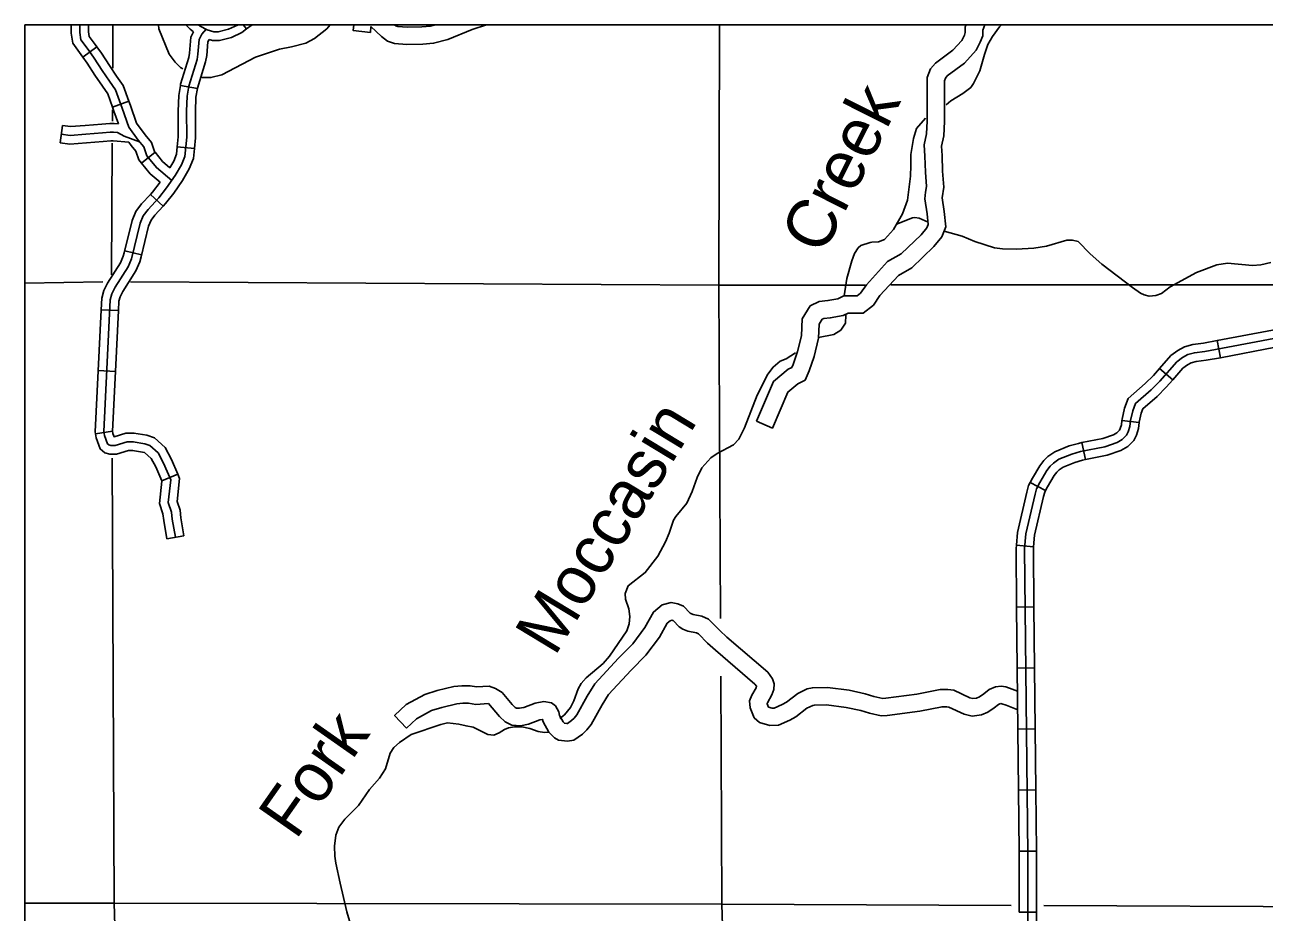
# Model space of a CAD drawing. Extents: x 1377389 to 1380723, y 1168351 to 1170484.
# Drawn here: x 1378340.6 to 1378554.8, y 1169425.9 to 1169579.4 of the extents above; entities that cross this region are included whole.
import ezdxf

# ---------------------------------------------------------------- set-up
doc = ezdxf.new("R2010")
doc.units = 0
doc.layers.add('B_Fill', color=7, linetype='Continuous')
doc.layers.add('B_Text', color=7, linetype='Continuous')

msp = doc.modelspace()

# ---------------------------------------------------------------- linework, layer by layer
at = {"layer": 'B_Fill'}
for p, q in [((1378378.92, 1169578.7), (1378378.37, 1169579.43)), ((1378350.63, 1169573.84), (1378353.04, 1169575.63)), ((1378367.5, 1169568.93), (1378370.45, 1169568.43)), ((1378355.77, 1169565.2), (1378358.6, 1169566.21)), ((1378346.73, 1169559.01), (1378347.11, 1169561.98)), ((1378360.79, 1169555.49), (1378363.12, 1169557.38)), ((1378369.95, 1169558), (1378366.97, 1169558.31)), ((1378362.33, 1169550.09), (1378364.52, 1169548.04)), ((1378360.79, 1169539.64), (1378357.88, 1169540.35)), ((1378353.8, 1169530.14), (1378356.8, 1169530)), ((1378546.71, 1169524.8), (1378547.27, 1169521.85)), ((1378356.29, 1169519.46), (1378353.3, 1169519.61)), ((1378536.76, 1169519.97), (1378539.02, 1169517.99)), ((1378530.26, 1169511.01), (1378533.24, 1169510.65)), ((1378352.82, 1169508.66), (1378355.78, 1169509.12)), ((1378523.34, 1169507.15), (1378523.93, 1169504.21)), ((1378367.04, 1169501.73), (1378364.28, 1169500.55)), ((1378514.41, 1169500.27), (1378517.05, 1169498.85)), ((1378368.12, 1169491.04), (1378365.17, 1169490.53)), ((1378512, 1169489.43), (1378514.99, 1169489.16)), ((1378512.05, 1169478.72), (1378515.05, 1169478.75)), ((1378512.16, 1169468.16), (1378515.16, 1169468.19)), ((1378512.27, 1169457.6), (1378515.27, 1169457.63)), ((1378512.37, 1169447.04), (1378515.37, 1169447.08)), ((1378512.48, 1169436.49), (1378515.48, 1169436.52)), ((1378512.51, 1169425.94), (1378515.51, 1169425.94))]:
    msp.add_line(p, q, dxfattribs=at)
for points in [[(1378348.6, 1169579.43), (1378348.63, 1169577.96), (1378348.89, 1169576.22), (1378350.33, 1169574.25), (1378350.63, 1169573.84)], [(1378350.1, 1169579.43), (1378350.13, 1169578.09), (1378350.32, 1169576.81), (1378351.54, 1169575.14), (1378352.63, 1169573.66), (1378353.98, 1169571.54), (1378355.26, 1169569.68), (1378356.29, 1169568.2), (1378357.44, 1169564.99), (1378358.6, 1169561.72), (1378360.2, 1169559.47), (1378361.17, 1169558.31), (1378361.68, 1169556.77), (1378363.35, 1169554.72), (1378366.01, 1169552.49)], [(1378351.6, 1169579.43), (1378351.63, 1169578.22), (1378351.75, 1169577.39), (1378352.75, 1169576.02), (1378353.04, 1169575.63)], [(1378355.85, 1169579.43), (1378355.81, 1169571.91)], [(1378363.74, 1169579.43), (1378363.8, 1169578.75), (1378365.58, 1169574.36), (1378366.63, 1169572.96), (1378367.54, 1169572.01), (1378367.93, 1169571.78)], [(1378368.43, 1169579.43), (1378369.18, 1169578.69), (1378369.8, 1169578.22)], [(1378370.64, 1169579.43), (1378370.95, 1169579.2), (1378372.13, 1169578.53), (1378373.27, 1169578.19), (1378374.05, 1169578.2), (1378375.84, 1169578.64), (1378377.35, 1169579.36), (1378377.44, 1169579.43)], [(1378370.99, 1169570.39), (1378371.29, 1169570.31), (1378372.79, 1169570.29), (1378374.68, 1169570.77), (1378380.51, 1169573.83), (1378384.62, 1169575.2), (1378386.71, 1169575.59), (1378389.18, 1169576.26), (1378390.68, 1169577.08), (1378392.8, 1169578.7), (1378393.42, 1169579.43)], [(1378372.48, 1169576.89), (1378373.06, 1169576.71), (1378374.24, 1169576.73), (1378376.34, 1169577.24), (1378378.11, 1169578.09), (1378378.92, 1169578.7)], [(1378378.92, 1169578.7), (1378379.89, 1169579.43)], [(1378397.47, 1169579.43), (1378397.36, 1169578.45), (1378400.34, 1169578.11)], [(1378400.45, 1169579.13), (1378400.34, 1169578.11)], [(1378400.45, 1169579.13), (1378402.26, 1169577.37), (1378403.33, 1169576.58), (1378404.49, 1169576.17), (1378406.63, 1169576.02), (1378409.39, 1169576.05), (1378411.26, 1169576.23), (1378413.73, 1169576.87), (1378417.94, 1169578.62), (1378420.44, 1169579.43)], [(1378404.52, 1169579.43), (1378404.75, 1169579.26), (1378405.11, 1169579.13), (1378406.72, 1169579.02), (1378409.23, 1169579.05), (1378410.74, 1169579.19), (1378411.64, 1169579.43)], [(1378460.58, 1169534.4), (1378460.7, 1169579.43)], [(1378503.32, 1169579.43), (1378503.18, 1169579.09), (1378503.18, 1169578.08), (1378503.01, 1169577.63), (1378502.55, 1169576.72), (1378501.04, 1169575.03), (1378498, 1169572.78), (1378497.15, 1169571.78), (1378496.56, 1169570.31), (1378496.56, 1169567.88), (1378496.56, 1169562.74), (1378496.47, 1169560.56), (1378496.06, 1169558.64), (1378496.17, 1169556.7), (1378496.27, 1169553.96), (1378496.45, 1169551.48), (1378496.28, 1169550.45), (1378496.16, 1169549.33)], [(1378506.58, 1169579.43), (1378506.18, 1169578.48), (1378506.18, 1169577.54), (1378505.76, 1169576.43), (1378505.05, 1169575.01), (1378503.06, 1169572.8), (1378500.06, 1169570.57), (1378499.75, 1169570.21), (1378499.56, 1169569.73), (1378499.56, 1169567.88), (1378499.56, 1169562.68), (1378499.45, 1169560.19), (1378499.08, 1169558.41), (1378499.17, 1169556.84), (1378499.26, 1169554.12), (1378499.47, 1169551.34), (1378499.16, 1169549.51)], [(1378499.89, 1169565.56), (1378500.7, 1169566.25), (1378502.74, 1169567.52), (1378504.11, 1169568.58), (1378504.58, 1169569.28), (1378505.71, 1169571.44), (1378506.49, 1169574.31), (1378507.07, 1169576), (1378507.85, 1169577.39), (1378509.09, 1169579.07), (1378509.44, 1169579.43)], [(1378371.95, 1169578.64), (1378371.22, 1169577.78), (1378370.77, 1169576.87), (1378370.54, 1169574.33), (1378370.38, 1169573.41), (1378368.97, 1169568.82), (1378368.67, 1169567.06), (1378368.58, 1169564.46), (1378368.62, 1169559.97), (1378368.28, 1169556.66), (1378367.67, 1169555.2), (1378366.6, 1169553.34), (1378365.13, 1169551.22), (1378363.79, 1169549.5), (1378361.92, 1169547.5), (1378361.09, 1169546.41), (1378360.55, 1169545.1), (1378359.05, 1169538.93), (1378358.46, 1169537.57), (1378356.21, 1169534.04), (1378355.65, 1169532.91), (1378355.36, 1169531.88), (1378354.27, 1169509.09), (1378354.38, 1169508.39), (1378354.89, 1169506.97), (1378355.15, 1169506.76), (1378355.51, 1169506.66), (1378356.25, 1169506.67), (1378358.32, 1169507.3), (1378359.36, 1169507.31), (1378361.35, 1169506.97), (1378362.24, 1169506.66)], [(1378369.8, 1169578.22), (1378369.33, 1169577.28), (1378369.08, 1169574.53), (1378368.94, 1169573.75), (1378367.54, 1169569.16), (1378367.5, 1169568.93)], [(1378372.48, 1169576.89), (1378372.27, 1169576.45), (1378372.06, 1169574.12), (1378371.86, 1169573.04), (1378370.46, 1169568.47), (1378370.45, 1169568.43)], [(1378353.04, 1169575.63), (1378353.87, 1169574.51), (1378355.23, 1169572.37), (1378356.49, 1169570.53), (1378357.63, 1169568.9), (1378358.6, 1169566.21)], [(1378350.63, 1169573.84), (1378351.39, 1169572.81), (1378352.73, 1169570.71), (1378354.03, 1169568.82), (1378354.94, 1169567.51), (1378355.77, 1169565.2)], [(1378367.5, 1169568.93), (1378367.21, 1169567.21), (1378367.11, 1169564.48), (1378367.14, 1169560.04), (1378366.97, 1169558.31)], [(1378370.45, 1169568.43), (1378370.2, 1169566.9), (1378370.11, 1169564.43), (1378370.14, 1169559.9), (1378369.95, 1169558)], [(1378358.6, 1169566.21), (1378358.86, 1169565.49), (1378359.94, 1169562.42), (1378361.39, 1169560.39), (1378362.5, 1169559.06), (1378363.02, 1169557.51), (1378363.12, 1169557.38)], [(1378355.76, 1169564.7), (1378355.75, 1169562.73)], [(1378355.77, 1169565.2), (1378356.03, 1169564.49), (1378356.8, 1169562.31)], [(1378347.11, 1169561.98), (1378348.5, 1169561.81), (1378351.03, 1169561.99), (1378353.9, 1169562.25), (1378355.32, 1169562.38), (1378356.04, 1169562.38), (1378356.8, 1169562.31)], [(1378493.78, 1169556.97), (1378494.22, 1169559.73), (1378494.76, 1169561.47), (1378496.27, 1169563.3)], [(1378346.92, 1169560.5), (1378348.46, 1169560.3), (1378351.15, 1169560.5), (1378354.04, 1169560.75), (1378355.39, 1169560.88), (1378355.97, 1169560.88), (1378356.61, 1169560.82), (1378357.76, 1169560.18), (1378360.42, 1169559.2)], [(1378346.73, 1169559.01), (1378348.42, 1169558.8), (1378351.27, 1169559), (1378354.18, 1169559.26), (1378355.46, 1169559.38), (1378355.89, 1169559.38), (1378358.62, 1169559.11)], [(1378355.73, 1169558.95), (1378355.59, 1169536.2)], [(1378358.62, 1169559.11), (1378359.01, 1169558.55), (1378359.83, 1169557.57), (1378360.34, 1169556.04), (1378360.79, 1169555.49)], [(1378363.12, 1169557.38), (1378364.42, 1169555.77), (1378365.69, 1169554.71)], [(1378369.95, 1169558), (1378369.77, 1169556.29), (1378369.05, 1169554.52), (1378367.89, 1169552.52), (1378366.36, 1169550.32), (1378364.95, 1169548.51), (1378364.52, 1169548.04)], [(1378366.97, 1169558.31), (1378366.83, 1169557.03), (1378366.35, 1169555.85), (1378365.69, 1169554.71)], [(1378360.79, 1169555.49), (1378362.27, 1169553.66), (1378364.02, 1169552.19)], [(1378487.01, 1169541.81), (1378488.18, 1169541.9), (1378489.21, 1169542.27), (1378490.75, 1169543.99), (1378492.33, 1169546.73), (1378493.2, 1169549.11), (1378493.69, 1169553.24), (1378493.79, 1169555.1), (1378493.78, 1169556.97)], [(1378364.02, 1169552.19), (1378362.67, 1169550.46), (1378362.33, 1169550.09)], [(1378362.33, 1169550.09), (1378360.79, 1169548.45), (1378359.81, 1169547.15), (1378359.15, 1169545.56), (1378357.79, 1169540.01)], [(1378499.16, 1169549.51), (1378499.55, 1169547.11), (1378499.83, 1169544.47), (1378499.13, 1169542.73), (1378497.75, 1169541.08), (1378493.91, 1169537.36), (1378491.61, 1169536.09), (1378488.43, 1169532.59), (1378487.31, 1169530.96), (1378485.55, 1169529.55), (1378484.09, 1169529.55), (1378482.91, 1169529.55), (1378482.09, 1169529.14), (1378479.82, 1169528.74), (1378478.75, 1169528.64), (1378478.44, 1169528.49), (1378477.93, 1169527.66), (1378477.83, 1169525.2), (1378477.07, 1169522.05), (1378476.2, 1169519.57), (1378475.49, 1169517.96), (1378474.22, 1169517.33), (1378472.52, 1169515.91), (1378469.84, 1169509.66), (1378467.09, 1169510.84)], [(1378496.16, 1169549.33), (1378496.57, 1169546.72), (1378496.77, 1169544.9), (1378496.52, 1169544.29), (1378495.55, 1169543.12), (1378492.11, 1169539.79), (1378489.72, 1169538.47), (1378486.08, 1169534.45), (1378485.09, 1169533.03), (1378484.5, 1169532.55), (1378484.09, 1169532.55), (1378482.2, 1169532.55), (1378481.14, 1169532.02), (1378479.42, 1169531.72), (1378477.91, 1169531.58), (1378476.34, 1169530.79), (1378474.97, 1169528.57), (1378474.84, 1169525.62), (1378474.19, 1169522.9), (1378473.41, 1169520.68), (1378473.18, 1169520.17), (1378472.57, 1169519.86), (1378470.05, 1169517.75), (1378467.09, 1169510.84)], [(1378364.52, 1169548.04), (1378363.09, 1169546.51), (1378362.43, 1169545.64), (1378362.01, 1169544.62), (1378360.71, 1169539.29)], [(1378491.29, 1169544.92), (1378494.03, 1169546.06), (1378494.43, 1169546.12), (1378495.19, 1169545.95), (1378496.73, 1169545.26)], [(1378499.52, 1169543.71), (1378502.62, 1169542.86), (1378504.84, 1169541.93), (1378508.25, 1169540.85), (1378509.61, 1169540.65), (1378512, 1169540.6), (1378515.05, 1169540.79), (1378517.22, 1169541.16), (1378520.74, 1169542.17), (1378521.68, 1169542.2), (1378522.68, 1169541.97), (1378524.78, 1169539.79), (1378526.75, 1169538.02), (1378532.05, 1169533.96), (1378533.44, 1169532.99), (1378534.08, 1169532.7), (1378534.98, 1169532.51), (1378536.11, 1169532.59), (1378537.07, 1169532.96), (1378538.57, 1169534.12), (1378543.13, 1169536.6), (1378546.65, 1169537.9), (1378548.5, 1169538.18), (1378552.81, 1169537.8), (1378554.23, 1169537.89), (1378555.96, 1169538.33)], [(1378482.21, 1169532.55), (1378482.69, 1169535.52), (1378483.55, 1169538.61), (1378484.04, 1169539.86), (1378484.66, 1169540.83), (1378485.14, 1169541.27), (1378486.71, 1169541.79), (1378487.01, 1169541.81)], [(1378357.79, 1169540.01), (1378357.64, 1169539.4), (1378357.16, 1169538.26), (1378354.93, 1169534.76), (1378354.27, 1169533.44), (1378353.9, 1169532.12), (1378353.8, 1169530.14)], [(1378360.71, 1169539.29), (1378360.5, 1169538.45), (1378359.82, 1169536.85), (1378357.54, 1169533.28), (1378357.08, 1169532.35), (1378356.88, 1169531.64), (1378356.8, 1169530)], [(1378340.61, 1169534.73), (1378354.08, 1169534.96)], [(1378358.88, 1169534.97), (1378460.58, 1169534.4), (1378485.89, 1169534.41)], [(1378460.86, 1169476.75), (1378460.58, 1169534.4)], [(1378490.29, 1169534.42), (1378566.7, 1169534.46)], [(1378353.8, 1169530.14), (1378353.3, 1169519.59)], [(1378356.8, 1169530), (1378356.29, 1169519.45)], [(1378477.83, 1169525.34), (1378480.46, 1169525.87), (1378481.67, 1169526.62), (1378482.44, 1169527.79), (1378482.55, 1169529.21)], [(1378556.53, 1169525.15), (1378544.57, 1169522.9), (1378542.77, 1169522.7), (1378541.62, 1169522.38), (1378540.73, 1169521.87), (1378539.74, 1169521.14), (1378536.81, 1169517.78), (1378535.29, 1169516.28), (1378532.58, 1169513.93), (1378532.12, 1169512.68), (1378531.74, 1169510.97), (1378531.61, 1169509.93), (1378531.32, 1169509.05), (1378531.03, 1169508.44), (1378530.3, 1169507.69), (1378529.43, 1169507.18), (1378527.3, 1169506.45), (1378523.1, 1169505.6), (1378521.59, 1169505.18), (1378519.35, 1169504.27), (1378518.4, 1169503.62), (1378517.85, 1169503.07), (1378517.28, 1169502.31), (1378516.08, 1169500.27), (1378515.5, 1169499.18), (1378515.23, 1169498.24), (1378513.65, 1169491.39), (1378513.42, 1169488.81), (1378513.96, 1169436.06), (1378514.04, 1169404.99)], [(1378557.14, 1169526.73), (1378556.28, 1169526.6), (1378546.71, 1169524.8)], [(1378546.71, 1169524.8), (1378544.35, 1169524.36), (1378542.5, 1169524.15), (1378541.05, 1169523.75), (1378539.92, 1169523.11), (1378538.73, 1169522.23), (1378536.76, 1169519.97)], [(1378557.6, 1169523.77), (1378556.79, 1169523.64), (1378547.27, 1169521.85)], [(1378450.02, 1169487.51), (1378451.37, 1169490.02), (1378452.01, 1169491.51), (1378452.74, 1169493.75), (1378453.13, 1169494.39), (1378455.06, 1169496.7), (1378455.95, 1169498.71), (1378456.82, 1169501.14), (1378457.66, 1169502.79), (1378459.2, 1169504.51), (1378460.28, 1169505.25), (1378463.12, 1169506.8), (1378464.01, 1169507.78), (1378465.02, 1169509.69), (1378467.21, 1169515.38), (1378469.04, 1169519.01), (1378469.95, 1169520.22), (1378471.17, 1169521.26), (1378472.2, 1169521.67), (1378473.83, 1169522.66)], [(1378547.27, 1169521.85), (1378544.79, 1169521.39), (1378543.06, 1169521.19), (1378542.21, 1169520.96), (1378541.57, 1169520.59), (1378540.78, 1169520.01), (1378539.02, 1169517.99)], [(1378353.3, 1169519.59), (1378352.79, 1169509.01), (1378352.82, 1169508.66)], [(1378356.29, 1169519.45), (1378355.78, 1169509.12)], [(1378536.76, 1169519.97), (1378535.73, 1169518.79), (1378534.29, 1169517.36), (1378531.33, 1169514.79), (1378530.7, 1169513.1), (1378530.29, 1169511.22), (1378530.26, 1169511.01)], [(1378539.02, 1169517.99), (1378537.92, 1169516.73), (1378536.33, 1169515.16), (1378533.88, 1169513.03), (1378533.59, 1169512.24), (1378533.25, 1169510.71), (1378533.24, 1169510.65)], [(1378530.26, 1169511.01), (1378530.17, 1169510.25), (1378529.95, 1169509.6), (1378529.81, 1169509.3), (1378529.38, 1169508.86), (1378528.81, 1169508.53), (1378526.92, 1169507.88), (1378523.34, 1169507.15)], [(1378533.24, 1169510.65), (1378533.11, 1169509.6), (1378532.74, 1169508.47), (1378532.3, 1169507.55), (1378531.25, 1169506.48), (1378530.07, 1169505.78), (1378527.7, 1169504.98), (1378523.93, 1169504.21)], [(1378352.82, 1169508.66), (1378352.92, 1169508.01), (1378353.62, 1169506.08), (1378354.45, 1169505.39), (1378355.33, 1169505.16), (1378356.48, 1169505.17), (1378358.55, 1169505.8), (1378359.24, 1169505.81), (1378361.33, 1169505.46)], [(1378355.78, 1169509.12), (1378355.84, 1169508.76), (1378356.05, 1169508.18), (1378358.09, 1169508.79), (1378359.47, 1169508.81), (1378361.73, 1169508.43), (1378363.02, 1169507.98)], [(1378366.65, 1169490.78), (1378366.1, 1169493.92), (1378365.96, 1169495.15), (1378365.42, 1169496.79), (1378365.83, 1169500.74), (1378364.6, 1169503.61), (1378363.65, 1169505.38), (1378362.24, 1169506.66)], [(1378367.04, 1169501.73), (1378365.95, 1169504.26), (1378364.85, 1169506.32), (1378363.02, 1169507.98)], [(1378523.34, 1169507.15), (1378522.76, 1169507.03), (1378521.12, 1169506.58), (1378518.65, 1169505.58), (1378517.45, 1169504.76), (1378516.73, 1169504.04), (1378516.05, 1169503.12), (1378514.8, 1169500.99), (1378514.41, 1169500.27)], [(1378355.72, 1169504.46), (1378356.08, 1169427.5)], [(1378364.28, 1169500.55), (1378363.25, 1169502.95), (1378362.45, 1169504.44), (1378361.33, 1169505.46)], [(1378523.93, 1169504.21), (1378523.46, 1169504.11), (1378522.08, 1169503.73), (1378520.07, 1169502.92), (1378519.38, 1169502.44), (1378519, 1169502.07), (1378518.55, 1169501.46), (1378517.41, 1169499.52), (1378517.05, 1169498.85)], [(1378368.12, 1169491.04), (1378367.59, 1169494.13), (1378367.44, 1169495.47), (1378366.94, 1169496.95), (1378367.36, 1169500.97), (1378367.04, 1169501.73)], [(1378365.17, 1169490.53), (1378364.62, 1169493.71), (1378364.49, 1169494.82), (1378363.89, 1169496.62), (1378364.3, 1169500.51), (1378364.28, 1169500.55)], [(1378514.41, 1169500.27), (1378514.12, 1169499.74), (1378513.8, 1169498.6), (1378512.19, 1169491.62), (1378512, 1169489.43)], [(1378517.05, 1169498.85), (1378516.92, 1169498.6), (1378516.71, 1169497.86), (1378515.16, 1169491.15), (1378514.99, 1169489.16)], [(1378512, 1169489.43), (1378511.95, 1169488.86), (1378512.05, 1169478.72)], [(1378514.99, 1169489.16), (1378514.95, 1169488.75), (1378515.05, 1169478.75)], [(1378433.09, 1169459.44), (1378433.87, 1169460.09), (1378434.91, 1169461.35), (1378435.52, 1169462.48), (1378436.25, 1169464.55), (1378436.78, 1169465.51), (1378437.64, 1169466.47), (1378440.57, 1169468.94), (1378441.69, 1169470.22), (1378444.65, 1169474.62), (1378445.1, 1169475.79), (1378445.2, 1169477.07), (1378445.01, 1169478.39), (1378444.43, 1169480.08), (1378444.4, 1169481.04), (1378444.9, 1169482.41), (1378447.87, 1169484.69), (1378450.02, 1169487.51)], [(1378512.2, 1169464.17), (1378511.3, 1169464.53), (1378510.21, 1169464.92), (1378509.35, 1169465.05), (1378508.38, 1169464.93), (1378507.3, 1169464.47), (1378506.39, 1169463.69), (1378505.62, 1169463.2), (1378505.13, 1169462.98), (1378504.5, 1169462.9), (1378503.97, 1169463.02), (1378501.17, 1169464.34), (1378500.15, 1169464.48), (1378498.85, 1169464.46), (1378494.82, 1169463.68), (1378489.43, 1169462.94), (1378488.9, 1169462.92), (1378487.37, 1169463.25), (1378485.87, 1169463.73), (1378483.08, 1169464.33), (1378479.37, 1169464.81), (1378476.74, 1169464.75), (1378475.83, 1169464.56), (1378474.21, 1169463.79), (1378472.27, 1169462.25), (1378471.53, 1169461.87), (1378470.15, 1169461.25), (1378469.78, 1169461.23), (1378469.16, 1169461.42), (1378468.94, 1169461.96), (1378468.93, 1169462.05), (1378468.98, 1169462.16), (1378469.76, 1169463.51), (1378470.08, 1169464.45), (1378470.15, 1169465.41), (1378469.86, 1169466.33), (1378469.02, 1169467.44), (1378461.96, 1169473.53), (1378460.72, 1169474.65), (1378458.81, 1169476.61), (1378457.64, 1169477.12), (1378456.11, 1169477.44), (1378455.75, 1169477.6), (1378455.62, 1169477.67), (1378454.46, 1169478.87), (1378453.5, 1169479.3), (1378452.34, 1169479.5), (1378450.79, 1169479.11), (1378449.29, 1169477.86), (1378447.79, 1169475.16), (1378445.7, 1169472.34), (1378443.25, 1169469.9), (1378439.13, 1169465.44), (1378437.8, 1169463.31), (1378436.03, 1169460.1), (1378435.56, 1169459.51), (1378435.11, 1169459.08), (1378434.39, 1169458.59), (1378434.33, 1169458.58), (1378433.87, 1169458.62), (1378433.65, 1169458.86), (1378433.05, 1169459.95), (1378432.91, 1169460.57), (1378432.37, 1169461.61), (1378431.63, 1169462.15), (1378430.33, 1169462.36), (1378428.85, 1169462.1), (1378426.85, 1169461.37), (1378426.09, 1169461.22), (1378425.6, 1169461.25), (1378425.37, 1169461.37), (1378424.85, 1169461.85), (1378423.12, 1169463.92)], [(1378512.05, 1169478.72), (1378512.16, 1169468.16)], [(1378515.05, 1169478.75), (1378515.16, 1169468.19)], [(1378512.23, 1169460.93), (1378510.24, 1169461.73), (1378509.49, 1169462), (1378509.31, 1169462.02), (1378509.16, 1169462), (1378508.9, 1169461.89), (1378508.18, 1169461.28), (1378507.05, 1169460.55), (1378505.95, 1169460.07), (1378504.35, 1169459.85), (1378502.97, 1169460.18), (1378500.31, 1169461.43), (1378499.97, 1169461.48), (1378499.16, 1169461.47), (1378495.31, 1169460.72), (1378489.69, 1169459.95), (1378488.64, 1169459.91), (1378486.6, 1169460.35), (1378485.1, 1169460.83), (1378482.57, 1169461.37), (1378479.21, 1169461.8), (1378477.09, 1169461.76), (1378476.8, 1169461.7), (1378475.8, 1169461.23), (1378473.91, 1169459.72), (1378472.83, 1169459.16), (1378470.87, 1169458.29), (1378469.41, 1169458.21), (1378467.58, 1169458.77), (1378466.67, 1169459.57), (1378465.98, 1169461.27), (1378465.89, 1169462.51), (1378466.27, 1169463.47), (1378467.01, 1169464.76), (1378467.1, 1169465.01), (1378466.82, 1169465.37), (1378459.97, 1169471.28), (1378458.64, 1169472.49), (1378457.07, 1169474.09), (1378456.72, 1169474.25), (1378455.21, 1169474.57), (1378454.37, 1169474.92), (1378453.73, 1169475.32), (1378452.71, 1169476.37), (1378452.62, 1169476.41), (1378452.46, 1169476.43), (1378452.19, 1169476.36), (1378451.64, 1169475.91), (1378450.32, 1169473.53), (1378447.97, 1169470.37), (1378445.41, 1169467.82), (1378441.53, 1169463.61), (1378440.39, 1169461.79), (1378438.53, 1169458.43), (1378437.78, 1169457.48), (1378437.01, 1169456.74), (1378435.51, 1169455.72), (1378434.41, 1169455.55), (1378432.85, 1169455.71), (1378432.16, 1169456.08), (1378431.21, 1169457.07), (1378430.22, 1169458.88), (1378430.12, 1169459.28), (1378429.64, 1169459.19), (1378427.66, 1169458.47), (1378426.28, 1169458.2), (1378424.77, 1169458.3), (1378423.63, 1169458.89), (1378422.67, 1169459.78), (1378420.77, 1169462.05)], [(1378512.16, 1169468.16), (1378512.27, 1169457.6)], [(1378515.16, 1169468.19), (1378515.27, 1169457.63)], [(1378461.09, 1169427.33), (1378460.91, 1169466.74)], [(1378423.12, 1169463.92), (1378421.96, 1169464.66), (1378420.86, 1169465.06), (1378418.7, 1169464.91), (1378417.57, 1169465.08), (1378416.18, 1169465.11), (1378414.77, 1169464.95), (1378411.9, 1169464.27), (1378409.74, 1169463.58), (1378406.53, 1169461.84), (1378404.53, 1169459.94), (1378406.6, 1169457.77)], [(1378420.77, 1169462.05), (1378418.58, 1169461.89), (1378417.31, 1169462.09), (1378416.31, 1169462.11), (1378415.29, 1169461.99), (1378412.7, 1169461.37), (1378410.92, 1169460.81), (1378408.31, 1169459.39), (1378406.6, 1169457.77)], [(1378396.92, 1169423.87), (1378396.29, 1169426.03), (1378395.1, 1169430.98), (1378394.38, 1169434.43), (1378394.19, 1169435.61), (1378394.14, 1169437.39), (1378394.4, 1169439.24), (1378394.9, 1169440.65), (1378395.93, 1169442.06), (1378398.31, 1169444.39), (1378400.22, 1169447.16), (1378401.93, 1169449.12), (1378402.97, 1169450.75), (1378403.79, 1169453.47), (1378404.4, 1169454.43), (1378405.37, 1169455.31), (1378407.41, 1169456.69), (1378412.53, 1169458.42), (1378413.69, 1169458.69), (1378415.62, 1169458.48), (1378416.9, 1169458.15), (1378418.12, 1169457.97), (1378420.65, 1169456.66), (1378421.67, 1169456.57), (1378422.62, 1169456.96), (1378423.54, 1169457.53), (1378424.23, 1169457.84), (1378425.25, 1169458.01), (1378426.52, 1169458.01), (1378427.88, 1169457.71), (1378429.32, 1169457.2), (1378430.42, 1169457.02), (1378431.2, 1169457.08)], [(1378512.27, 1169457.6), (1378512.37, 1169447.04)], [(1378515.27, 1169457.63), (1378515.37, 1169447.08)], [(1378512.37, 1169447.04), (1378512.48, 1169436.49)], [(1378515.37, 1169447.08), (1378515.48, 1169436.52)], [(1378512.48, 1169436.49), (1378512.49, 1169436.06), (1378512.51, 1169425.94)], [(1378515.48, 1169436.52), (1378515.49, 1169436.07), (1378515.51, 1169425.94)], [(1378340.61, 1169427.53), (1378356.08, 1169427.5), (1378461.09, 1169427.33), (1378511.13, 1169427.11)], [(1378359.16, 1169322.83), (1378356.08, 1169427.5)], [(1378462.88, 1169370.04), (1378461.09, 1169427.33)], [(1378516.74, 1169427.09), (1378567.27, 1169426.87)], [(1378515.51, 1169425.94), (1378515.54, 1169415.38)]]:
    msp.add_lwpolyline(points, dxfattribs=at)
at = {"layer": 'B_Text'}
msp.add_lwpolyline([(1378340.61, 1169579.43), (1379848.03, 1169579.43), (1379848.03, 1168702.1), (1378340.61, 1168702.1)], close=True, dxfattribs=at)

# ---------------------------------------------------------------- texts
at = {"layer": 'B_Fill'}
for s, rotation, p in [('Creek', 63.1868, (1378478.52, 1169539.35)), ('Moccasin', 58.7709, (1378432.21, 1169470.03)), ('Fork', 54.9692, (1378387.46, 1169438.29))]:
    msp.add_text(s, height=8.448, rotation=rotation, dxfattribs=at).set_placement(p)

doc.saveas('drawing.dxf')
